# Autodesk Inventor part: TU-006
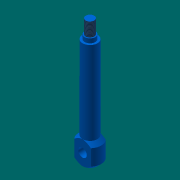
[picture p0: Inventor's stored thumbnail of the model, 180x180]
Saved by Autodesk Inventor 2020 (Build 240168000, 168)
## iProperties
Created: 2002-07
Part Number: TU-006
Document SubType Name: Modeling
Designer: PN
Description: Piston Rod
Density: 8.08 g/cm^3
Mass: 144.065 g
Surface Area: 58.412 cm^2
Volume: 17.8299 cm^3
Material: Stainless Steel
Appearance: 0,128,255
Control State: 0
Master: False
Checked Out: False
Shininess: 64.0
Angle Display Precision: 2
Document Length Units: 11269
Document Angle Units: 11279
Document Time Units: 11290
Document Mass Units: 11286
Document Length Units Precision: 3
Document Angle Units Precision: 2
Compacted: True
LENGTH: 1.000 in
Density: 0.0
Volumn: 0.0
Area: 0.0
PropertySet Name: Model Information
Author: PN
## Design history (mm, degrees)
sketch "Sketch1"
  geometry: L1 (0, 117)-(4, 117); L2 (10.5, 0)-(0, 0); L3 (7, 100)-(7, 22); L4 (5, 100)-(7, 100); L5 (5, 104)-(5, 100); L6 (4, 104)-(5, 104); L7 (4, 117)-(4, 104); L8 (10.5, 22)-(10.5, 0); L9 (0, 117)-(0, 0); L10 (7, 22)-(10.5, 22); 1 further point
  constraints: 20 end point, 6 parallel, 3 perpendicular, 1 coincident, 1 vertical
  dimensions: "d10" = 21 diameter of L8 L9; "d11" = 14 diameter of L3 L9; "d12" = 22 distance of L8.start L2.start; "d13" = 100 distance from line of L3.start L2; "d14" = 104 distance between parallel lines of L6 L2; "d15" = 117 distance between parallel lines of L2 L1; "d16" = 8 diameter of L7 L9; "d17" = 10 diameter of L5 L9
revolve "Revolution1" sketch "Sketch1" stored, may be unused: angle "d0" = 90 deg
sketch "Sketch2"
  geometry: L1 (-10.5, 22)-(-10.5, 0) reference; L2 (10.5, 22)-(10.5, 0) reference; L3 (-10.5, 11)-(10.5, 11); C1 r 4 at (0, 11)
  constraints: 3 midpoint, 2 end point, 1 centre point
  dimensions: "d1" = 8 diameter of C1
sketch "Sketch3"
  geometry: 2 further points
hole "Hole1" sketch "Sketch3" at (0, 0) diameter "d25" = 8; stored, may be unused: countersink angle "d29" = 90 deg, drill point angle "d31" = 118 deg; dims "d26" = 6, "d27" = 4, "d28" = 2, "d30" = 8
mirror "Mirror1"
chamfer "Chamfer1" distance "d18" = 3.5; stored, may be unused: second distance "d19" = 2, angle "d20" = 45 deg
body "Solid1"
workplane "Work Plane1"
workplane "Work Plane2"
sketch "Sketch4"
  geometry: L1 (-10.5, -39)-(10.5, -39) reference; L2 (-10.5, -61)-(10.5, -61) reference; L3 (-10.5, -61)-(-10.5, -39); L4 (10.5, -61)-(10.5, -39); 1 further point
  constraints: 4 end point, 1 parallel, 1 perpendicular
extrude "Extrusion1" cut sketch "Sketch4" extent not by distance; stored distance "d21" = 10; taper "d22" = 0 deg
thread "Thread1" dims "d23" = 10, "d24" = 0
other parameters: "LENGTH" = 25.4 [user parameter]
